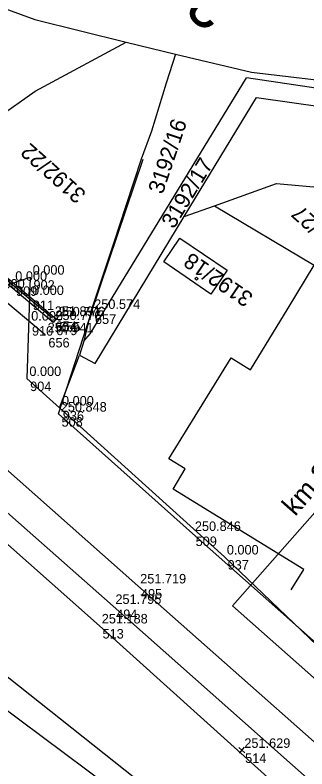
# Model space of a CAD drawing. Extents: x -496688 to -495455, y -1089309 to -1088026.
# Drawn here: x -495578.4 to -495541.6, y -1088998.4 to -1088903.4 of the extents above; entities that cross this region are included whole.
import ezdxf

# ---------------------------------------------------------------- set-up
doc = ezdxf.new("R2010")
doc.units = 0
for name, color, linetype in [('Vrstva 1', 7, 'Continuous'), ('Vrstva 12', 7, 'Continuous'), ('Vrstva 17', 7, 'Continuous'), ('Vrstva 23', 7, 'Continuous'), ('Vrstva 49', 7, 'Continuous'), ('Vrstva 51', 7, 'Continuous'), ('Vrstva 53', 7, 'Continuous'), ('Vrstva 55', 7, 'Continuous'), ('Vrstva 57', 7, 'Continuous'), ('Vrstva 59', 7, 'Continuous'), ('Vrstva 60', 7, 'Continuous'), ('Vrstva 61', 7, 'Continuous'), ('Vrstva 7', 7, 'Continuous')]:
    doc.layers.add(name, color=color, linetype=linetype)

msp = doc.modelspace()

# ---------------------------------------------------------------- linework, layer by layer
at = {"layer": 'Vrstva 1'}
msp.add_line((-495516.783, -1088939.025), (-495550.981, -1088977.862), dxfattribs=at)
for points in [[(-495527.086, -1089012.404), (-495566.062, -1088977.925), (-495589.962, -1088956.794), (-495616.745, -1088933.093), (-495637.54, -1088914.691), (-495671.404, -1088884.738), (-495682.523, -1088874.895), (-495703.405, -1088856.411), (-495732.455, -1088830.711)], [(-495524.281, -1089009.522), (-495562.935, -1088975.342), (-495586.745, -1088954.297), (-495614.132, -1088930.012)], [(-495512.653, -1089011.747), (-495514.818, -1089009.84), (-495550.981, -1088977.862)]]:
    msp.add_lwpolyline(points, dxfattribs=at)
at = {"layer": 'Vrstva 12'}
msp.add_lwpolyline([(-495573.242, -1088941.658), (-495573.634, -1088942.125), (-495592.62, -1088926.159), (-495604.259, -1088916.294), (-495613.794, -1088908.066), (-495643.24, -1088883.292), (-495643.338, -1088883.406), (-495643.718, -1088883.082), (-495657.949, -1088870.946), (-495657.56, -1088870.489), (-495643.329, -1088882.625), (-495613.503, -1088907.723), (-495592.252, -1088925.716), (-495573.242, -1088941.658)], dxfattribs=at)
at = {"layer": 'Vrstva 17'}
for points in [[(-495517.748, -1089002.67), (-495556.033, -1088968.721), (-495572.958, -1088953.669), (-495568.738, -1088940.716), (-495562.255, -1088921.518)], [(-495573.718, -1088941.604), (-495592.699, -1088925.826)]]:
    msp.add_lwpolyline(points, dxfattribs=at)
at = {"layer": 'Vrstva 23'}
for p, q in [((-495559.66, -1088934.5), (-495557.64, -1088931.5)), ((-495557.64, -1088931.5), (-495551.67, -1088935.55)), ((-495553.71, -1088938.55), (-495559.66, -1088934.5)), ((-495551.67, -1088935.55), (-495553.71, -1088938.55))]:
    msp.add_line(p, q, dxfattribs=at)
at = {"layer": 'Vrstva 49'}
msp.add_lwpolyline([(-495529.937, -1089014.416), (-495567.785, -1088980.384), (-495591.33, -1088959.551), (-495639.387, -1088917.342), (-495674.135, -1088887.188), (-495686.874, -1088874.363), (-495688.359, -1088873.072), (-495708.421, -1088858.602)], dxfattribs=at)
at = {"layer": 'Vrstva 51'}
msp.add_line((-495574.617, -1088943.674), (-495593.927, -1088927.637), dxfattribs=at)
at = {"layer": 'Vrstva 53'}
for p, q in [((-495592.02, -1088941.81), (-495576.5, -1088936.4)), ((-495576.5, -1088936.4), (-495576.92, -1088949.18)), ((-495576.92, -1088949.18), (-495572.8, -1088952.9)), ((-495572.8, -1088952.9), (-495552, -1088971.69)), ((-495552, -1088971.69), (-495515.63, -1089006.49)), ((-495560.92, -1089004.84), (-495588.83, -1088984.09)), ((-495560.92, -1089004.84), (-495588.83, -1088984.09))]:
    msp.add_line(p, q, dxfattribs=at)
at = {"layer": 'Vrstva 55'}
for p, q in [((-495598.81, -1088895.61), (-495575.95, -1088903.93)), ((-495575.95, -1088903.93), (-495564.39, -1088906.78)), ((-495575.9, -1088912.96), (-495564.39, -1088906.78)), ((-495564.39, -1088906.78), (-495558.19, -1088908.3)), ((-495558.19, -1088908.3), (-495559.37, -1088911.94)), ((-495558.19, -1088908.3), (-495548.6, -1088910.54)), ((-495548.6, -1088910.54), (-495527.2, -1088913.16)), ((-495568.95, -1088943.54), (-495549.23, -1088911.29)), ((-495536.61, -1088913.13), (-495549.23, -1088911.29)), ((-495559.37, -1088911.94), (-495561.2, -1088917.99)), ((-495589.39, -1088922.42), (-495575.9, -1088912.96)), ((-495557.07, -1088928.76), (-495547.97, -1088913.76)), ((-495547.97, -1088913.76), (-495536.93, -1088915.3)), ((-495561.2, -1088917.99), (-495562.49, -1088921.52)), ((-495562.49, -1088921.52), (-495564.44, -1088927.4)), ((-495553.25, -1088927.4), (-495545.45, -1088924.61)), ((-495545.45, -1088924.61), (-495525.28, -1088926.32)), ((-495564.44, -1088927.4), (-495565.94, -1088932.04)), ((-495557.07, -1088928.76), (-495553.25, -1088927.4)), ((-495553.25, -1088927.4), (-495540.66, -1088934.92)), ((-495568.32, -1088947.29), (-495557.07, -1088928.76)), ((-495565.94, -1088932.04), (-495568.88, -1088940.74)), ((-495543.97, -1088940.34), (-495540.66, -1088934.92)), ((-495548.7, -1088948.08), (-495543.97, -1088940.34)), ((-495568.88, -1088940.74), (-495569.73, -1088944.48)), ((-495569.73, -1088944.48), (-495568.95, -1088943.54)), ((-495569.73, -1088944.48), (-495570.31, -1088946.26)), ((-495572.8, -1088952.9), (-495570.31, -1088946.26)), ((-495570.31, -1088946.26), (-495568.32, -1088947.29)), ((-495559.03, -1088959.33), (-495551.17, -1088946.6)), ((-495551.17, -1088946.6), (-495548.7, -1088948.08)), ((-495614.49, -1088959.01), (-495560.21, -1089002)), ((-495556.96, -1088960.59), (-495559.03, -1088959.33)), ((-495558.49, -1088963.14), (-495556.96, -1088960.59)), ((-495541.97, -1088973.29), (-495558.49, -1088963.14)), ((-495543.59, -1088975.85), (-495541.97, -1088973.29)), ((-495543.59, -1088975.85), (-495543.59, -1088975.85))]:
    msp.add_line(p, q, dxfattribs=at)
at = {"layer": 'Vrstva 59'}
msp.add_circle((-495555.523, -1088936.602), 0.175, dxfattribs=at)
at = {"layer": 'Vrstva 60'}
for p, q in [((-495576.5, -1088936.4), (-495576.5, -1088936.4)), ((-495576.5, -1088936.4), (-495576.5, -1088936.4)), ((-495576.58, -1088938.96), (-495576.58, -1088938.96)), ((-495576.58, -1088938.96), (-495576.58, -1088938.96)), ((-495568.738, -1088940.716), (-495568.738, -1088940.716)), ((-495568.738, -1088940.716), (-495568.738, -1088940.716)), ((-495576.69, -1088942.19), (-495576.69, -1088942.19)), ((-495576.69, -1088942.19), (-495576.69, -1088942.19)), ((-495573.718, -1088941.604), (-495573.718, -1088941.604)), ((-495573.718, -1088941.604), (-495573.718, -1088941.604)), ((-495573.634, -1088942.125), (-495573.634, -1088942.125)), ((-495573.634, -1088942.125), (-495573.634, -1088942.125)), ((-495573.242, -1088941.658), (-495573.242, -1088941.658)), ((-495573.242, -1088941.658), (-495573.242, -1088941.658)), ((-495574.617, -1088943.674), (-495574.617, -1088943.674)), ((-495574.617, -1088943.674), (-495574.617, -1088943.674)), ((-495576.92, -1088949.18), (-495576.92, -1088949.18)), ((-495576.92, -1088949.18), (-495576.92, -1088949.18)), ((-495572.958, -1088953.669), (-495572.958, -1088953.669)), ((-495572.958, -1088953.669), (-495572.958, -1088953.669)), ((-495572.8, -1088952.9), (-495572.8, -1088952.9)), ((-495572.8, -1088952.9), (-495572.8, -1088952.9)), ((-495556.033, -1088968.721), (-495556.033, -1088968.721)), ((-495556.033, -1088968.721), (-495556.033, -1088968.721)), ((-495552, -1088971.69), (-495552, -1088971.69)), ((-495552, -1088971.69), (-495552, -1088971.69)), ((-495562.935, -1088975.342), (-495562.935, -1088975.342)), ((-495562.935, -1088975.342), (-495562.935, -1088975.342)), ((-495566.062, -1088977.925), (-495566.062, -1088977.925)), ((-495566.062, -1088977.925), (-495566.062, -1088977.925)), ((-495567.785, -1088980.384), (-495567.785, -1088980.384)), ((-495567.785, -1088980.384), (-495567.785, -1088980.384)), ((-495549.79, -1088996.072), (-495549.79, -1088996.072)), ((-495549.79, -1088996.072), (-495549.79, -1088996.072))]:
    msp.add_line(p, q, dxfattribs=at)
at = {"layer": 'Vrstva 7'}
for p, q in [((-495549.416, -1088996.403), (-495550.164, -1088995.741)), ((-495550.121, -1088996.446), (-495549.459, -1088995.698))]:
    msp.add_line(p, q, dxfattribs=at)

# ---------------------------------------------------------------- texts
at = {"layer": 'Vrstva 1'}
msp.add_text('km 28.284', height=2.5, rotation=48.63392, dxfattribs=at).set_placement((-495543.078, -1088966.66))
at = {"layer": 'Vrstva 57'}
for s, rotation, p in [('3192/16', 71.34062, (-495559.798, -1088926.045)), ('3192/22', 138.45394, (-495569.332, -1088925.79)), ('3192/17', 58.55535, (-495558.385, -1088930.419)), ('3192/27', 138.45394, (-495535.144, -1088933.573)), ('3192/18', 145.75797, (-495548.234, -1088938.653))]:
    msp.add_text(s, height=2, rotation=rotation, dxfattribs=at).set_placement(p)
at = {"layer": 'Vrstva 60'}
for s, p in [('902', (-495576.1, -1088938)), ('902', (-495576.1, -1088938)), ('909', (-495578.3, -1088938.77)), ('909', (-495578.3, -1088938.77)), ('911', (-495576.18, -1088940.56)), ('911', (-495576.18, -1088940.56)), ('657', (-495568.338, -1088942.316)), ('657', (-495568.338, -1088942.316)), ('654', (-495573.318, -1088943.204)), ('654', (-495573.318, -1088943.204)), ('655', (-495572.842, -1088943.258)), ('655', (-495572.842, -1088943.258)), ('910', (-495576.29, -1088943.79)), ('910', (-495576.29, -1088943.79)), ('679', (-495573.234, -1088943.725)), ('679', (-495573.234, -1088943.725)), ('656', (-495574.217, -1088945.274)), ('656', (-495574.217, -1088945.274)), ('904', (-495576.52, -1088950.78)), ('904', (-495576.52, -1088950.78)), ('936', (-495572.4, -1088954.5)), ('936', (-495572.4, -1088954.5)), ('508', (-495572.558, -1088955.269)), ('508', (-495572.558, -1088955.269)), ('509', (-495555.633, -1088970.321)), ('509', (-495555.633, -1088970.321)), ('937', (-495551.6, -1088973.29)), ('937', (-495551.6, -1088973.29)), ('495', (-495562.535, -1088976.942)), ('495', (-495562.535, -1088976.942)), ('494', (-495565.662, -1088979.525)), ('494', (-495565.662, -1088979.525)), ('513', (-495567.385, -1088981.984)), ('513', (-495567.385, -1088981.984)), ('514', (-495549.39, -1088997.672)), ('514', (-495549.39, -1088997.672))]:
    msp.add_text(s, height=1.2, dxfattribs=at).set_placement(p)
at = {"layer": 'Vrstva 61'}
for s, p in [('0.000', (-495576.2, -1088936.1)), ('0.000', (-495576.2, -1088936.1)), ('0.000', (-495578.4, -1088936.87)), ('0.000', (-495578.4, -1088936.87)), ('0.000', (-495581.22, -1088937.85)), ('0.000', (-495581.22, -1088937.85)), ('0.000', (-495576.28, -1088938.66)), ('0.000', (-495576.28, -1088938.66)), ('250.574', (-495568.438, -1088940.416)), ('250.574', (-495568.438, -1088940.416)), ('251.891', (-495573.418, -1088941.304)), ('251.891', (-495573.418, -1088941.304)), ('250.776', (-495572.942, -1088941.358)), ('250.776', (-495572.942, -1088941.358)), ('0.000', (-495576.39, -1088941.89)), ('0.000', (-495576.39, -1088941.89)), ('250.776', (-495573.334, -1088941.825)), ('250.776', (-495573.334, -1088941.825)), ('250.941', (-495574.317, -1088943.374)), ('250.941', (-495574.317, -1088943.374)), ('0.000', (-495576.62, -1088948.88)), ('0.000', (-495576.62, -1088948.88)), ('0.000', (-495572.5, -1088952.6)), ('0.000', (-495572.5, -1088952.6)), ('250.848', (-495572.658, -1088953.369)), ('250.848', (-495572.658, -1088953.369)), ('250.846', (-495555.733, -1088968.421)), ('250.846', (-495555.733, -1088968.421)), ('0.000', (-495551.7, -1088971.39)), ('0.000', (-495551.7, -1088971.39)), ('251.719', (-495562.635, -1088975.042)), ('251.719', (-495562.635, -1088975.042)), ('251.795', (-495565.762, -1088977.625)), ('251.795', (-495565.762, -1088977.625)), ('251.188', (-495567.485, -1088980.084)), ('251.188', (-495567.485, -1088980.084)), ('251.629', (-495549.49, -1088995.772)), ('251.629', (-495549.49, -1088995.772))]:
    msp.add_text(s, height=1.2, dxfattribs=at).set_placement(p)
at = {"layer": 'Vrstva 7'}
msp.add_text('289.1', height=6, rotation=138.49349, dxfattribs=at).set_placement((-495549.996, -1088901.359))

doc.saveas('drawing.dxf')
